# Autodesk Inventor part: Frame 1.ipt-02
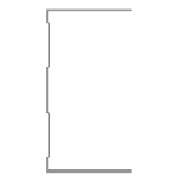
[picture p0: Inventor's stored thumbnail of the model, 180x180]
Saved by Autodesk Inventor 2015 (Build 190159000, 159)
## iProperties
IsCustomPart: 1
Created: 2015-04
Part Number: Frame 1.ipt-02
Material: Aluminum 6061
Description: Kévin Novo
Document SubType Name: Modeling
Standard: Kevin
Designer: suporte
Standards Organization: Kevin
Language: en-US
Size Designation: (Unnamed 2)
Categories: <MemberInstance><Categories><Category DisplayName="Structural Shapes" InternalName="089c4875-fa83-4c05-b084-43b9cc11f5ed" Mnemonic="GRDR"><CategoryParameter Dis
Density: 2.7 g/cm^3
Appearance: Aluminum - Flat
_CCFamilyMember: 2
_CCFamilyDisplayName: Kévin - Kévin Novo
_FrameMemberDoc: Frame Member File
_Version: 15.0.0
_GetPNFromCC: 1
G_W: 50,000 mm
G_H: 75,000 mm
G_L: 2100,000 mm
+93953822-904C-4BF3-B0FF-2A5B89CD50CC+CUTDETAIL1: Notch
Author: suporte
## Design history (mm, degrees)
node "Start Plane"
node "End Plane"
sketch "Sketch"
  geometry: L1 (24.7, 37.5)-(24.7, 36.9); L2 (24.7, 36.9)-(-24.7, 36.9); L3 (-24.7, -36.9)-(24.7, -36.9); L4 (24.7, -36.9)-(24.7, -37.5); L5 (24.7, -37.5)-(-25.3, -37.5); L6 (-25.3, 37.5)-(24.7, 37.5); L7 (-24.7, 36.9)-(-24.7, 31.9); L8 (-24.7, 31.9)-(-23.3, 30.5); L9 (-23.3, 30.5)-(-23.3, 10.934); L10 (-23.3, 10.934)-(-24.7, 9.534); L11 (-24.7, 9.534)-(-24.7, -9.534); L12 (-24.7, -9.534)-(-23.3, -10.934); L13 (-23.3, -10.934)-(-23.3, -30.5); L14 (-23.3, -30.5)-(-24.7, -31.9); L15 (-24.7, -31.9)-(-24.7, -36.9); L16 (-25.3, -37.5)-(-25.3, -31.651); L17 (-25.3, -31.651)-(-23.9, -30.251); L18 (-23.9, -30.251)-(-23.9, -11.183); L19 (-23.9, -11.183)-(-25.3, -9.783); L20 (-25.3, -9.783)-(-25.3, 9.783); L21 (-25.3, 9.783)-(-23.9, 11.183); L22 (-23.9, 11.183)-(-23.9, 30.251); L23 (-23.9, 30.251)-(-25.3, 31.651); L24 (-25.3, 31.651)-(-25.3, 37.5); L25 (-25.3, 0)-(30.37, 0); 3 further points
  constraints: 50 end point, 10 point on line, 9 parallel, 5 perpendicular, 4 equal length, 3 midpoint, 3 vertical, 2 vertical alignment, 1 collinear, 1 horizontal, 1 horizontal alignment
  dimensions: "d3" = 0.6 distance of L1.start L1.end (= d6); "d5" = 75 distance between parallel lines of L5 L6; "d6" = 0.6 distance between parallel lines of L24 L7 (= d8); "d7" = 0.6 distance between parallel lines of L8 L23 (= d8); "d8" = 0.6 distance between parallel lines of L22 L9 (= d12); "Espessura" = 0.6 distance between parallel lines of L17 L14; "d10" = 0.6 distance between parallel lines of L13 L18 (= Espessura); "d11" = 0.6 distance between parallel lines of L12 L19 (= Espessura); "d12" = 0.6 distance between parallel lines of L21 L10 (= d11); "d13" = 5 distance of L2.end L7.end; "d15" = 135 deg angle of L9 L8; "d16" = 2 distance between parallel lines of L24 L9; "d17" = 50 distance of L6.start L1.start
extrude "Body" join sketch "Sketch" stored distance "d24" = 0.13; taper "d25" = 0 deg
node "Driven Length"
  sketch "Sketch10"
    geometry: L1 (0, 0)-(10, 0) reference
    constraints: 2 end point, 1 horizontal
  workplane "Work Plane7"
  sketch "Sketch11"
    geometry: L1 (-2, 0)-(12, 0) reference; L2 (-2, 2100)-(12, 2100) reference
    dimensions: "d27" = 2100 distance between parallel lines of L1 L2 (derived)
workplane "Work Plane8"
workplane "Work Plane9"
workplane "Work Plane10"
sketch "Sketch12"
  geometry: L1 (24.7, 37.5)-(24.7, 36.9); L2 (24.7, 36.9)-(-24.7, 36.9); L3 (-24.7, 36.9)-(-24.7, 31.9); L4 (-24.7, 31.9)-(-23.3, 30.5); L5 (-23.3, 30.5)-(-23.3, 10.934); L6 (-23.3, 10.934)-(-24.7, 9.534); L7 (-24.7, 9.534)-(-24.7, -9.534); L8 (-24.7, -9.534)-(-23.3, -10.934); L9 (-23.3, -10.934)-(-23.3, -30.5); L10 (-23.3, -30.5)-(-24.7, -31.9); L11 (-24.7, -31.9)-(-24.7, -36.9); L12 (-24.7, -36.9)-(24.7, -36.9); L13 (24.7, -36.9)-(24.7, -37.5); L14 (24.7, -37.5)-(-25.3, -37.5); L15 (-25.3, -37.5)-(-25.3, -31.651); L16 (-25.3, -31.651)-(-23.9, -30.251); L17 (-23.9, -30.251)-(-23.9, -11.183); L18 (-23.9, -11.183)-(-25.3, -9.783); L19 (-25.3, -9.783)-(-25.3, 9.783); L20 (-25.3, 9.783)-(-23.9, 11.183); L21 (-23.9, 11.183)-(-23.9, 30.251); L22 (-23.9, 30.251)-(-25.3, 31.651); L23 (-25.3, 31.651)-(-25.3, 37.5); L24 (-25.3, 37.5)-(24.7, 37.5)
  constraints: 48 end point, 10 point on line
extrude "Extrusion3" cut sketch "Sketch12" stored distance "d36" = 0.13; taper "d37" = 0 deg
body "Solid1"
other parameters: "G_OFFSET_START" = 0 [user parameter; used in 1 equation term], "G_OFFSET_END" = 0 [user parameter; used in 1 equation term], "d22" = 0 (computed from G_OFFSET_START), "G_L" = 2100 (= d27) [user parameter], "d34" = 90 deg
